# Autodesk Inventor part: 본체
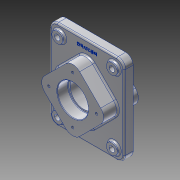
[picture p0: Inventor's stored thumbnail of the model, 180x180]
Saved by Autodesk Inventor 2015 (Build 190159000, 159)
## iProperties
Created: 2026-07
Part Number: 본체
Material: 알루미늄 6061
Document SubType Name: Modeling
Designer: USER
Density: 2.7 g/cm^3
Appearance: 알루미늄 - 평지
Mass: 2132.41 g
Surface Area: 955.114 cm^2
Volume: 789.782 cm^3
Author: USER
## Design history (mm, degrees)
sketch "스케치1"
  geometry: L1 (75, 90)-(-75, 90); L2 (-75, 90)-(-75, -90); L3 (-75, -90)-(75, -90); L4 (75, -90)-(75, 90); L5 (75, 90)-(-75, -90); L6 (-75, 90)-(75, -90); 1 further point
  constraints: 12 end point, 2 midpoint, 2 parallel, 1 horizontal, 1 perpendicular
  dimensions: "d0" = 150 distance of L3.end L2.end; "d1" = 180 distance of L2.end L1.end
extrude "돌출1" new body sketch "스케치1" stored distance "d2" = 18; taper "d3" = 0 deg
sketch "스케치2"
  geometry: L1 (-14.142, 56.569)-(-56.569, 14.142); L2 (-56.569, -14.142)-(-14.142, -56.569); L3 (14.142, -56.569)-(56.569, -14.142); L4 (56.569, 14.142)-(14.142, 56.569); A1 r 20 centre (0, 42.426) between (14.142, 56.569) and (-14.142, 56.569); A2 r 20 centre (-42.426, 0) between (-56.569, 14.142) and (-56.569, -14.142); A3 r 20 centre (42.426, 0) between (56.569, -14.142) and (56.569, 14.142); A4 r 20 centre (0, -42.426) between (-14.142, -56.569) and (14.142, -56.569); 5 further points
  constraints: 8 end point, 8 point on circle, 8 point on line, 8 tangent, 4 centre point, 3 equal radius, 2 horizontal alignment, 2 parallel, 2 vertical alignment
  dimensions: "d6" = 100 distance between parallel lines of L3 L1; "d7" = 100 distance of point (0, 70.711) point (-70.711, 0); "d8" = 20 radius of A1
extrude "돌출2" join sketch "스케치2" distance "d9" = 29; taper "d10" = 0 deg
sketch "스케치3"
  geometry: L1 (-56.569, -14.142)-(-14.142, -56.569) reference; L2 (14.142, -56.569)-(56.569, -14.142) reference; L3 (56.569, 14.142)-(14.142, 56.569) reference; L4 (-14.142, 56.569)-(-56.569, 14.142) reference; A1 r 20 centre (0, -42.426) between (-14.142, -56.569) and (14.142, -56.569) reference; A2 r 20 centre (42.426, 0) between (56.569, -14.142) and (56.569, 14.142) reference; A3 r 20 centre (0, 42.426) between (14.142, 56.569) and (-14.142, 56.569) reference; A4 r 20 centre (-42.426, 0) between (-56.569, 14.142) and (-56.569, -14.142) reference; 1 further point
extrude "돌출3" join sketch "스케치3" distance "d11" = 23; taper "d12" = 0 deg
fillet "모깎기1" dims "d13" = 15
hole "구멍2" diameter "d34" = 54; stored, may be unused: countersink angle "d38" = 90 deg, drill point angle "d40" = 0 deg; dims "d32" = 50, "d33" = 50, "d35" = 6, "d36" = 62, "d37" = 22, "d39" = 8
sketch "스케치6"
  geometry: L1 (-60, 90)-(60, 90) reference; L2 (75, 75)-(75, -75) reference; L3 (60, -90)-(-60, -90) reference; L4 (-75, -75)-(-75, 75) reference; L5 (14.142, 56.569)-(56.569, 14.142) reference; L6 (56.569, -14.142)-(14.142, -56.569) reference; L7 (-14.142, -56.569)-(-56.569, -14.142) reference; L8 (-56.569, 14.142)-(-14.142, 56.569) reference; L9 (-55, 70)-(55, 70); L10 (55, 70)-(55, -70); L11 (55, -70)-(-55, -70); L12 (-55, -70)-(-55, 70); C1 r 27 at (0, 0) reference; C2 r 11 at (-55, 70); A1 r 15 centre (-60, 75) between (-60, 90) and (-75, 75) reference; A2 r 15 centre (60, 75) between (75, 75) and (60, 90) reference; A3 r 15 centre (60, -75) between (60, -90) and (75, -75) reference; A4 r 15 centre (-60, -75) between (-75, -75) and (-60, -90) reference; A5 r 20 centre (0, 42.426) between (14.142, 56.569) and (-14.142, 56.569) reference; A6 r 20 centre (42.426, 0) between (56.569, -14.142) and (56.569, 14.142) reference; A7 r 20 centre (0, -42.426) between (-14.142, -56.569) and (14.142, -56.569) reference; A8 r 20 centre (-42.426, 0) between (-56.569, 14.142) and (-56.569, -14.142) reference; 2 further points
  constraints: 8 end point, 2 parallel, 1 centre point, 1 coincident, 1 horizontal, 1 midpoint, 1 perpendicular, 1 vertical alignment
  dimensions: "d52" = 110 distance of L10.end L11.end; "d53" = 140 distance of L9.end L10.end; "d54" = 20 distance between parallel lines of L9 L1; "d55" = 22 diameter of C2
extrude "돌출5" join sketch "스케치6" distance "d56" = 5; taper "d57" = 0 deg
hole "구멍4" diameter "d60" = 11; stored, may be unused: countersink angle "d64" = 90 deg, drill point angle "d66" = 0 deg; dims "d58" = 10, "d59" = 10, "d61" = 10, "d62" = 62, "d63" = 22, "d65" = 13
chamfer "모따기1" distance "d73" = 1; stored, may be unused: second distance "d74" = 2, angle "d75" = 45 deg
fillet "모깎기2" dims "d76" = 1
fillet "모깎기3" dims "d77" = 3
sketch "스케치7"
  geometry: L1 (60, 90)-(-60, 90) reference; 2 further points
  constraints: 1 vertical alignment, 1 other
  dimensions: "d78" = 15 distance from line of L1 point (0, 75)
feature "엠보싱1" sketch "스케치7" dims "d0" = 150, "d1" = 180, "d79" = 0.5, "d80" = 0
sketch "스케치11"
  geometry: L1 (0, 0)-(-48, 0)
  constraints: 2 end point, 1 horizontal
  dimensions: "d97" = 48 distance of L1.start L1.end
hole "구멍7" sketch "스케치11" at (-48, 0) diameter "d98" = 4.917; stored, may be unused: countersink angle "d102" = 90 deg, drill point angle "d104" = 118 deg; dims "d99" = 10, "d100" = 62, "d101" = 22, "d103" = 13
sketch "스케치13"
  geometry: 1 further point
hole "구멍9" sketch "스케치13" at (0, 0) diameter "d119" = 62; stored, may be unused: countersink angle "d123" = 90 deg, drill point angle "d125" = 0 deg; dims "d120" = 10, "d121" = 62, "d122" = 22, "d124" = 22
sketch "스케치14"
  geometry: L1 (0, 0)-(0, -48); C1 r 2.458 at (0, -48) reference
  constraints: 2 end point, 1 vertical
  dimensions: "d126" = 48 distance of L1.start L1.end (derived)
hole "구멍10" sketch "스케치14" at (0, -48) diameter "d127" = 4.917; stored, may be unused: countersink angle "d131" = 90 deg, drill point angle "d133" = 118 deg; dims "d128" = 10, "d129" = 62, "d130" = 22, "d132" = 13
fillet "모깎기4" dims "d137" = 1
chamfer "모따기2" distance "d138" = 1; stored, may be unused: second distance "d139" = 2, angle "d140" = 45 deg
node "솔리드1"
pattern_linear "직사각형 패턴2"
pattern_circular "원형 패턴2" dims angle "d106" = 360 deg
pattern_circular "원형 패턴4" dims angle "d135" = 360 deg
node "절단 모서리 투영1"
